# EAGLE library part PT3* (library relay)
Miniature Relay SCHRACK 3 pole 10 A DC- or AC-coil Source: http://www.schrack.com/.. 5823.pdf Socked 78603 Source: http://www.schrack.com/.. 5836.pdf
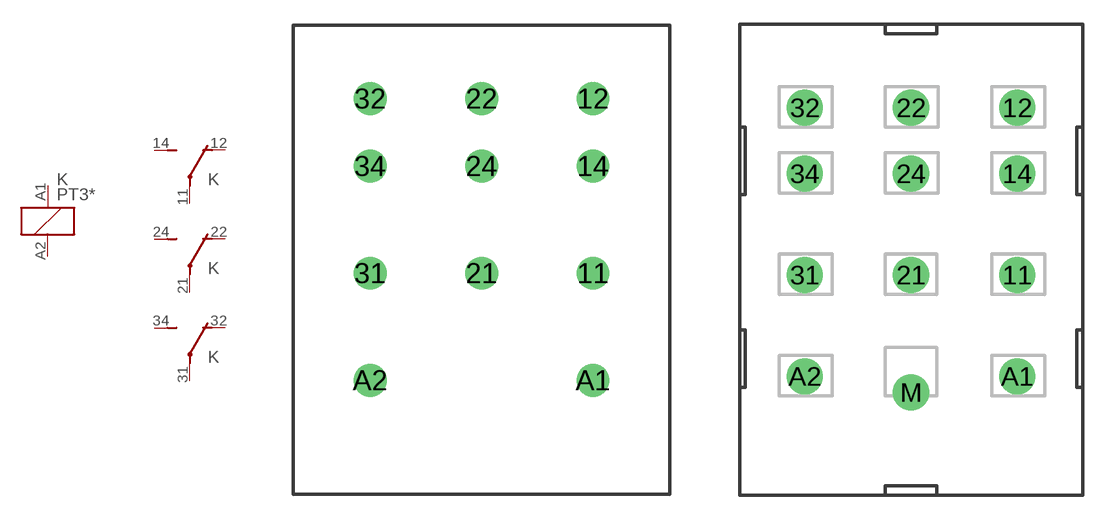
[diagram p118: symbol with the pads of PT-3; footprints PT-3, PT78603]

Designator prefix K; gates 1=K 2=U 3=U 4=U

## PT371R06 (OC_FARNELL: unknown; OC_NEWARK: unknown), PT371R12 (OC_FARNELL: unknown; OC_NEWARK: unknown), PT371R24 (OC_FARNELL: unknown; OC_NEWARK: unknown), PT371R48 (OC_FARNELL: unknown; OC_NEWARK: unknown), PT371R60 (OC_FARNELL: unknown; OC_NEWARK: unknown), PT371S15 (OC_FARNELL: unknown; OC_NEWARK: unknown), PT371T30 (OC_FARNELL: unknown; OC_NEWARK: unknown), PT381R06 (OC_FARNELL: unknown; OC_NEWARK: unknown), PT381R12 (OC_FARNELL: unknown; OC_NEWARK: unknown), PT381R24 (OC_FARNELL: unknown; OC_NEWARK: unknown), PT381R48 (OC_FARNELL: unknown; OC_NEWARK: unknown), PT381R60 (OC_FARNELL: unknown; OC_NEWARK: unknown), PT381S15 (OC_FARNELL: unknown; OC_NEWARK: unknown), PT381T30 (OC_FARNELL: unknown; OC_NEWARK: unknown), PT371506 (OC_FARNELL: unknown; OC_NEWARK: unknown), PT371512 (OC_FARNELL: unknown; OC_NEWARK: unknown), PT371524 (OC_FARNELL: unknown; OC_NEWARK: unknown), PT371548 (OC_FARNELL: unknown; OC_NEWARK: unknown), PT371560 (OC_FARNELL: unknown; OC_NEWARK: unknown), PT371615 (OC_FARNELL: unknown; OC_NEWARK: unknown), PT371730 (OC_FARNELL: unknown; OC_NEWARK: unknown), PT381506 (OC_FARNELL: unknown; OC_NEWARK: unknown), PT381512 (OC_FARNELL: unknown; OC_NEWARK: unknown), PT381524 (OC_FARNELL: unknown; OC_NEWARK: unknown), PT381548 (OC_FARNELL: unknown; OC_NEWARK: unknown), PT381560 (OC_FARNELL: unknown; OC_NEWARK: unknown), PT381615 (OC_FARNELL: unknown; OC_NEWARK: unknown), PT381730 (OC_FARNELL: unknown; OC_NEWARK: unknown)  [PT-3]
11  2:P  pas
12  2:O  pas
14  2:S  pas
21  3:P  pas
22  3:O  pas
24  3:S  pas
31  4:P  pas
32  4:O  pas
34  4:S  pas
A1  1:1  pas
A2  1:2  pas

## PT3-78603 (OC_FARNELL: unknown; OC_NEWARK: unknown)  [PT78603]
Pads as for PT-3

## Footprint PT-3 (pad centres in mm)
Miniature Relay SCHRACK 3 pole 10 A DC- or AC-coil Source: http://www.schrack.com/.. 5823.pdf
drill 1.3 round: 11 6.6,6.35; 12 6.6,16.7; 14 6.6,12.7; 21 0,6.35; 22 0,16.7; 24 0,12.7; 31 -6.6,6.35; 32 -6.6,16.7; 34 -6.6,12.7; A1 6.6,0; A2 -6.6,0

## Footprint PT78603 (pad centres in mm)
Accessories Miniature Relay PT SCHRACK Socket with PCB terminals 3 Pol. Source: http://www.schrack.com/.. 5836.pdf
drill 1.5 round: 11 6.6,6.3; 12 6.6,16.7; 14 6.6,12.6; 21 0,6.3; 22 0,16.7; 24 0,12.6; 31 -6.6,6.3; 32 -6.6,16.7; 34 -6.6,12.6; A1 6.6,0; A2 -6.6,0; M 0,-1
